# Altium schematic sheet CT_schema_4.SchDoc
size 556 x 419 mm
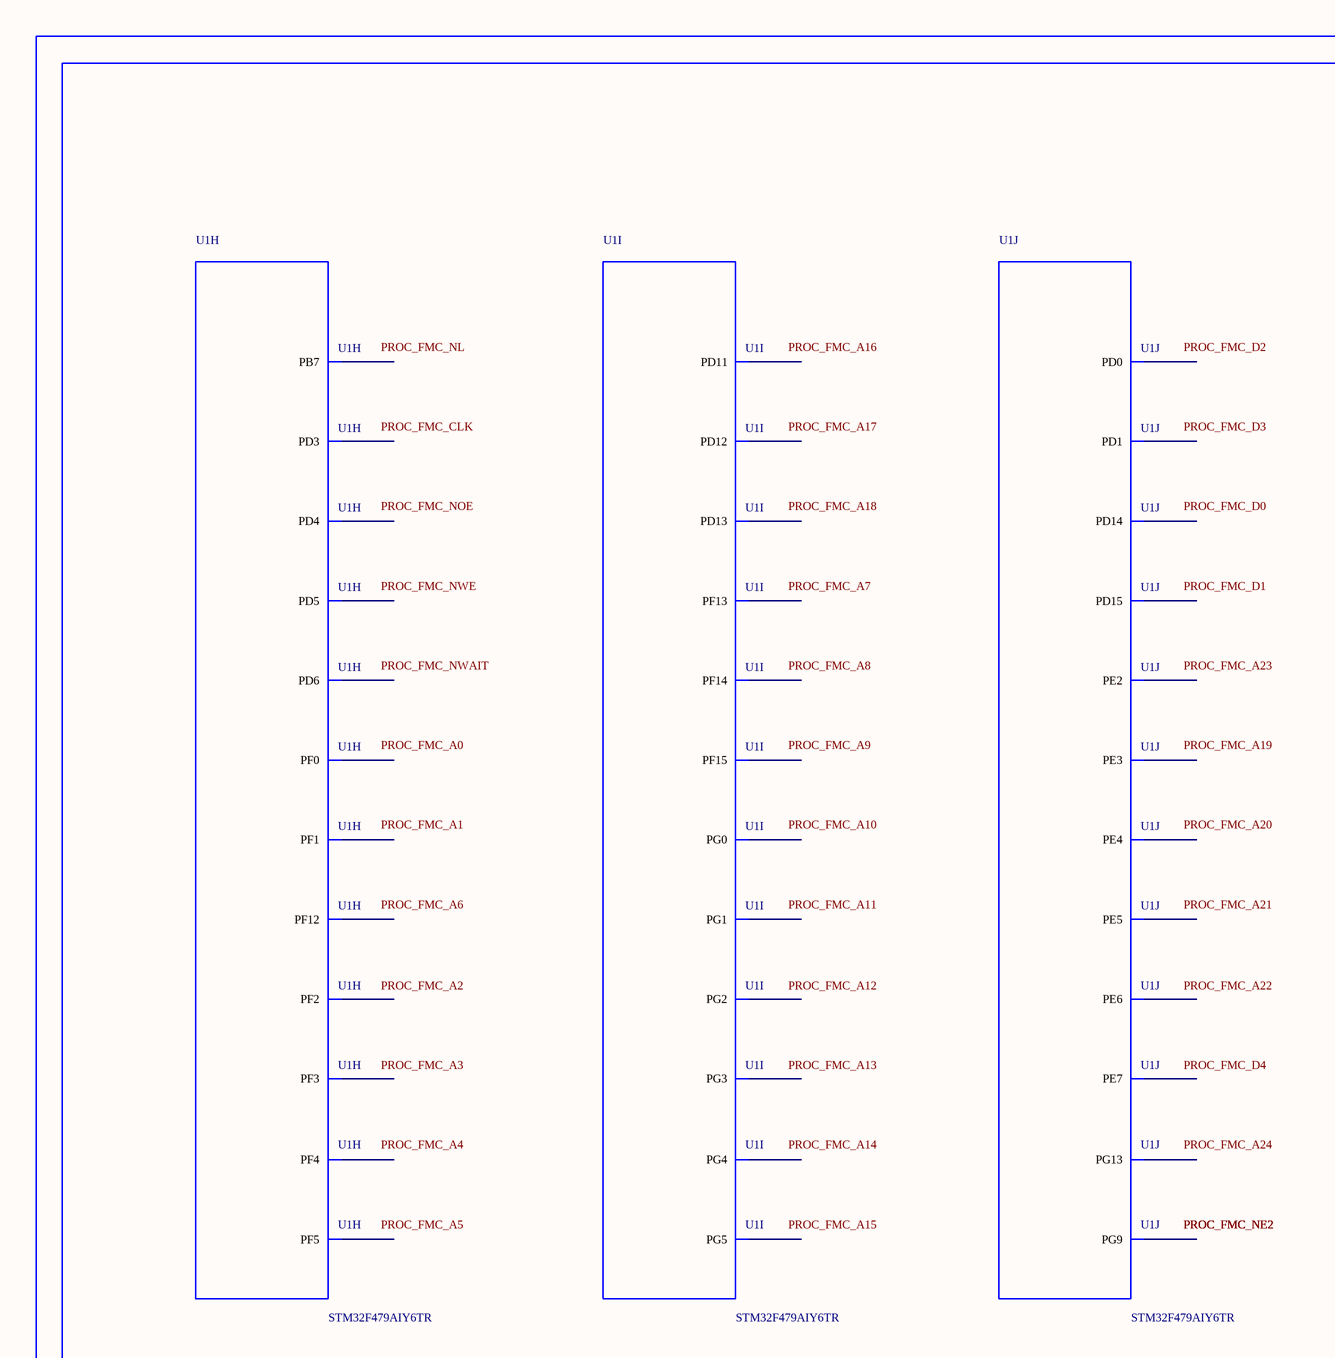
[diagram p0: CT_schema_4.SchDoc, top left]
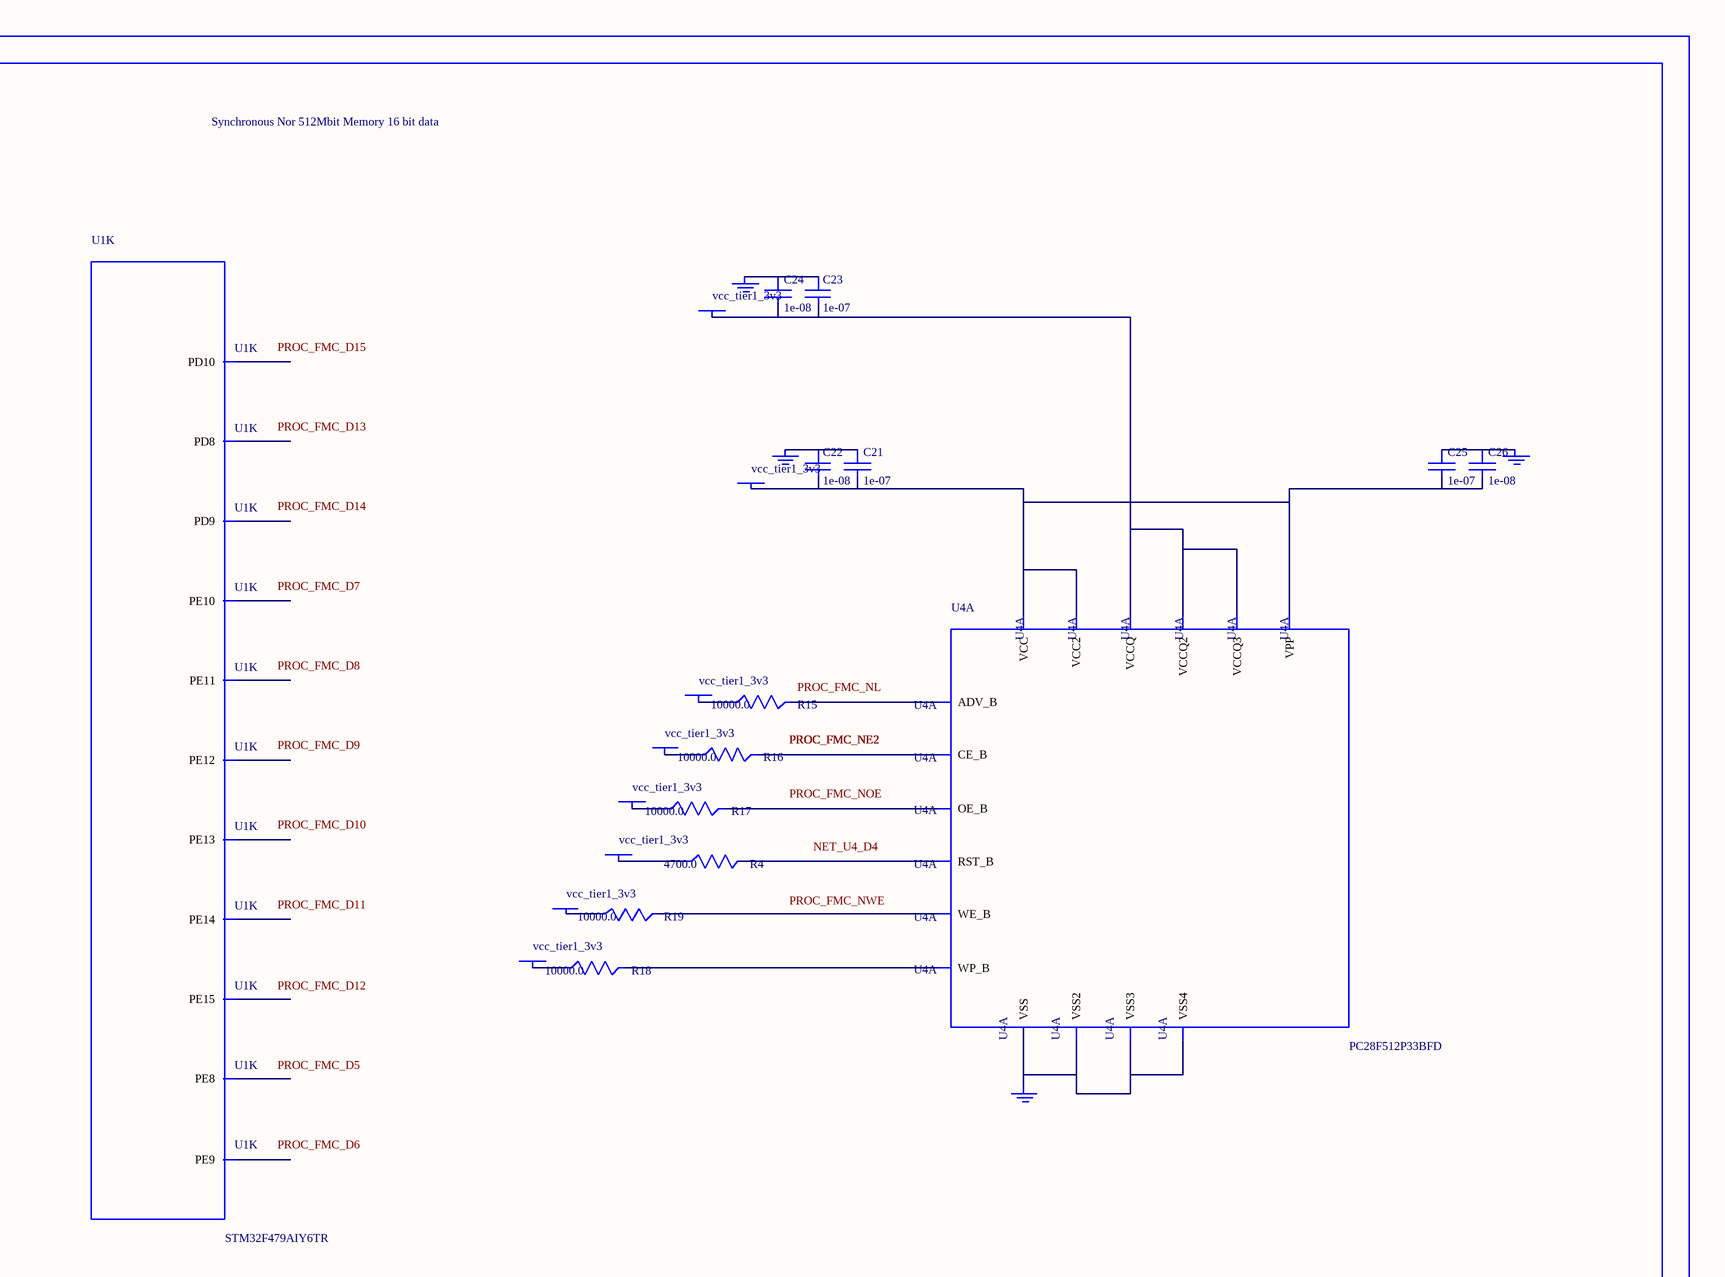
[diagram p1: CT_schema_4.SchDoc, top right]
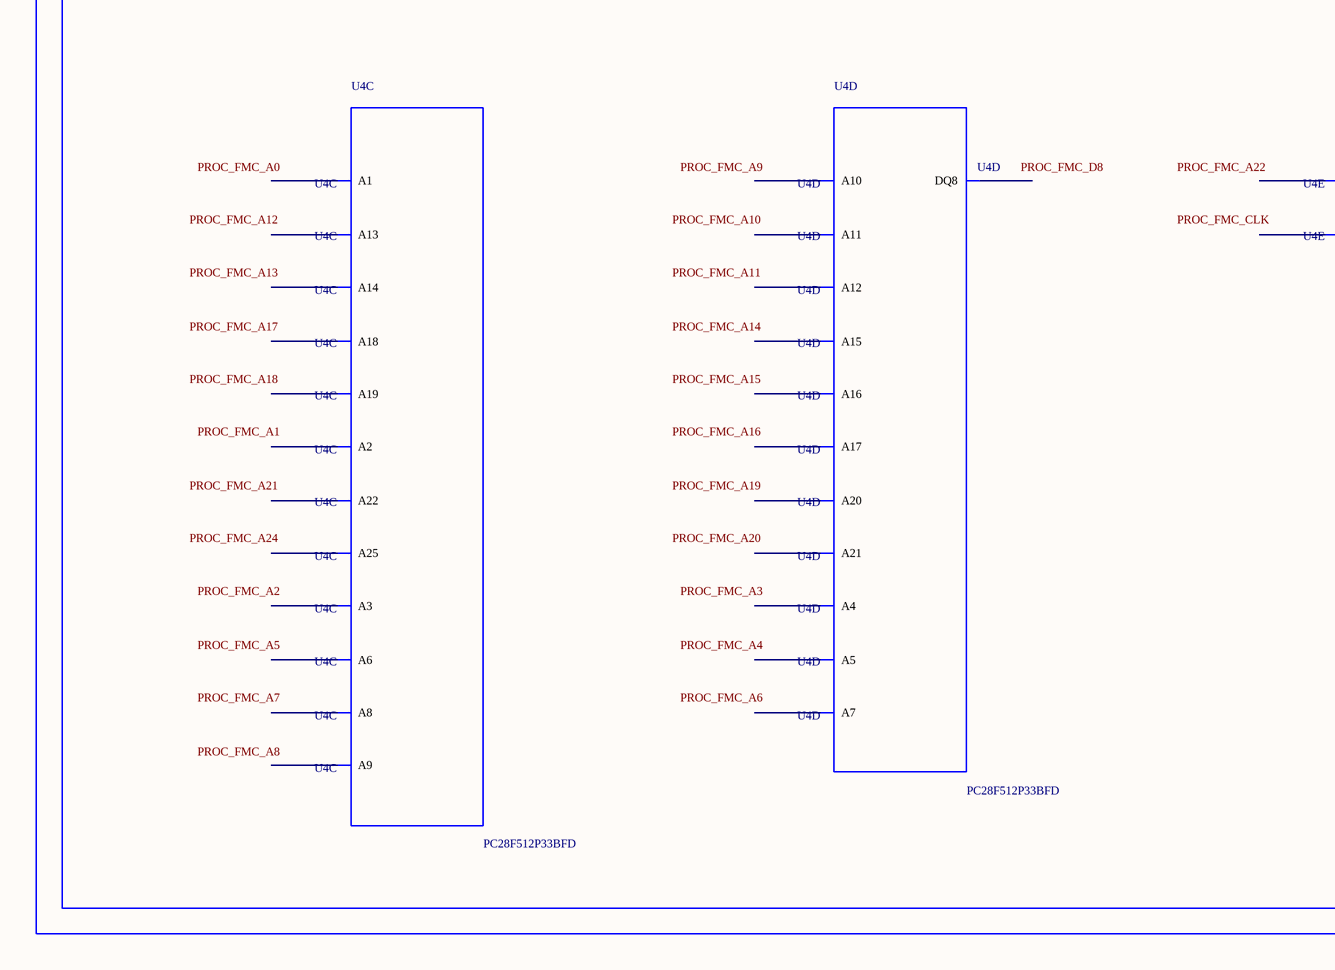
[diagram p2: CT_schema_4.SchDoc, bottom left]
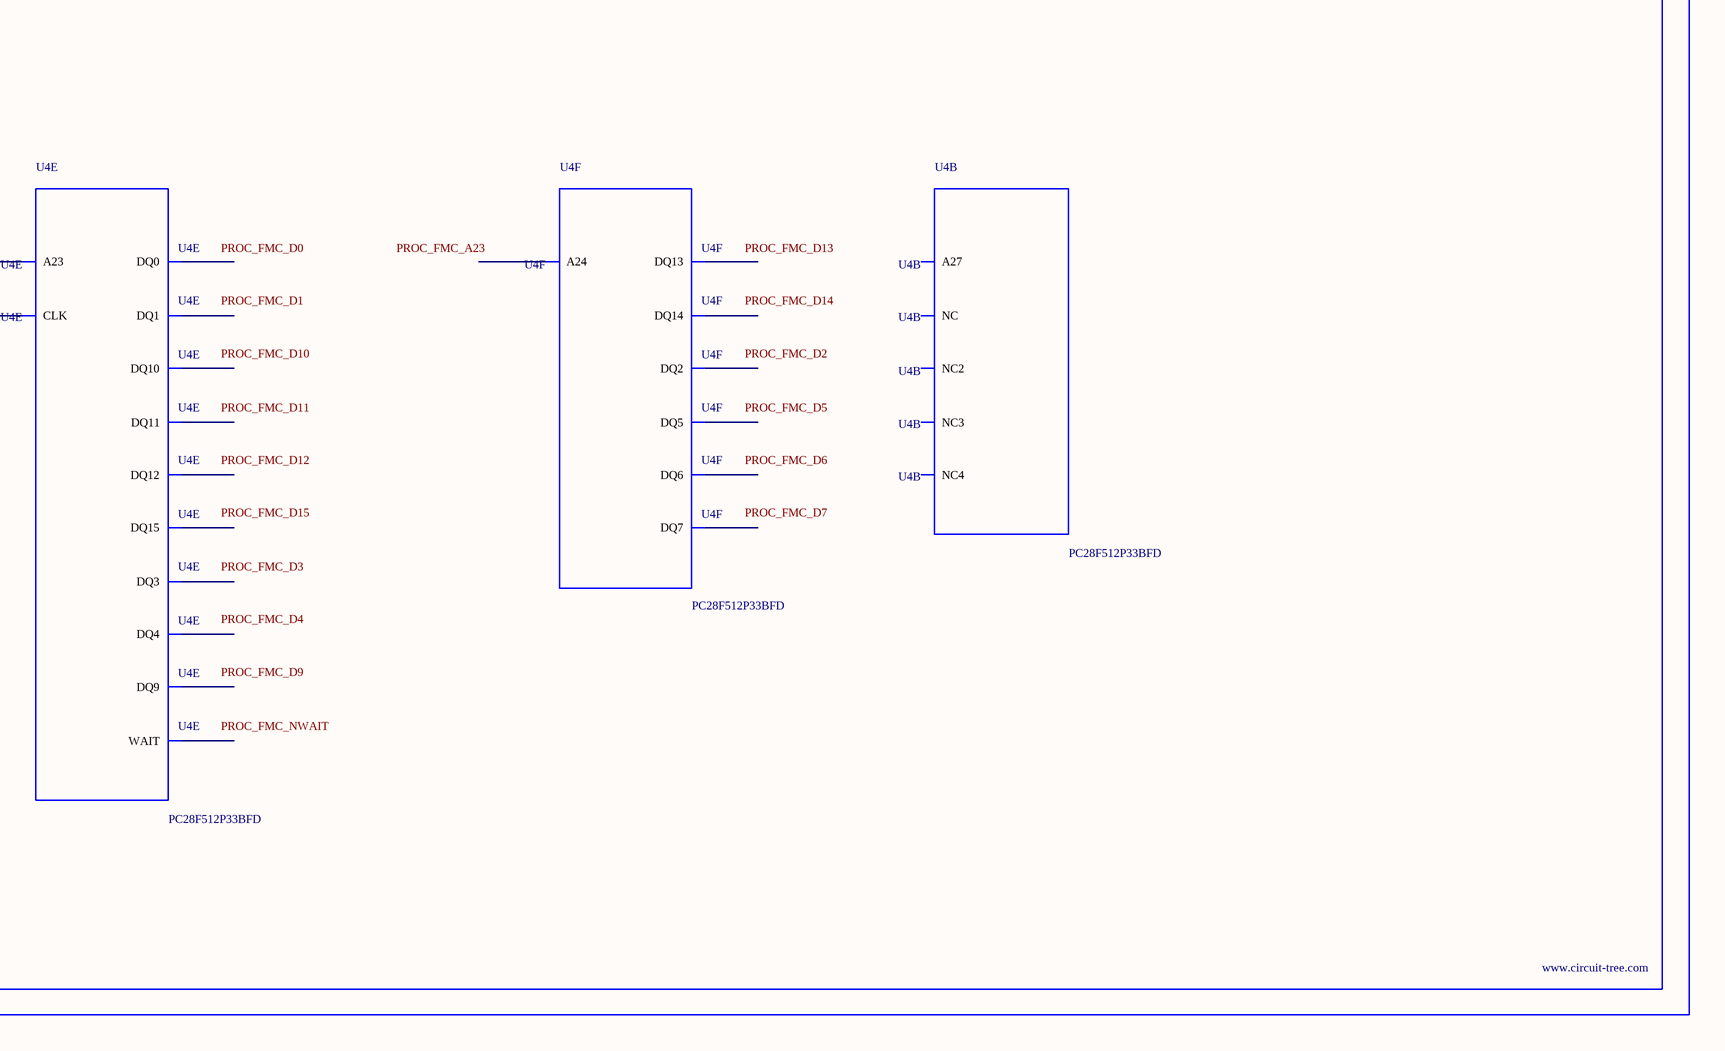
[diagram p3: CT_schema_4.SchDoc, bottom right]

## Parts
BORDER3  (no value)
C21  1e-07  [C0402]
C22  1e-08  [C0402]
C23  1e-07  [C0402]
C24  1e-08  [C0402]
C25  1e-07  [C0402]
C26  1e-08  [C0402]
GND_INSTANCE_3_0  (no value)
GND_INSTANCE_3_1  (no value)
GND_INSTANCE_3_2  (no value)
GND_INSTANCE_3_3  (no value)
POWER_INSTANCE_3_0  vcc_tier1_3v3
POWER_INSTANCE_3_1  vcc_tier1_3v3
POWER_INSTANCE_3_2  vcc_tier1_3v3
POWER_INSTANCE_3_3  vcc_tier1_3v3
POWER_INSTANCE_3_4  vcc_tier1_3v3
POWER_INSTANCE_3_5  vcc_tier1_3v3
POWER_INSTANCE_3_6  vcc_tier1_3v3
POWER_INSTANCE_3_7  vcc_tier1_3v3
R4  4700.0  [R0603]
R15  10000.0  [R0603]
R16  10000.0  [R0603]
R17  10000.0  [R0603]
R18  10000.0  [R0603]
R19  10000.0  [R0603]
U1  STM32F479AIY6TR  [WLCSP168]  (parts H,I,J,K of 13)
U4  PC28F512P33BFD  [PC28F512P33BFD]  (parts A,B,C,D,E,F of 6)

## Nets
NetC21_1: C21.1 C22.1 GND_INSTANCE_3_0.0(GND)
NetC21_2: C21.2 C22.2 C25.2 C26.2 POWER_INSTANCE_3_0.0(PWR) U4.A4(VPP) U4.A6(VCC) U4.H3(VCC2)
NetC23_1: C23.1 C24.1 GND_INSTANCE_3_1.0(GND)
NetC23_2: C23.2 C24.2 POWER_INSTANCE_3_1.0(PWR) U4.D5(VCCQ) U4.D6(VCCQ2) U4.G4(VCCQ3)
NetC25_1: C25.1 C26.1 GND_INSTANCE_3_2.0(GND)
NetGND_INSTANCE_3_3_0: GND_INSTANCE_3_3.0(GND) U4.B2(VSS) U4.H2(VSS2) U4.H4(VSS3) U4.H6(VSS4)
NetPOWER_INSTANCE_3_2_0: POWER_INSTANCE_3_2.0(PWR) R15.1
NetPOWER_INSTANCE_3_3_0: POWER_INSTANCE_3_3.0(PWR) R16.1
NetPOWER_INSTANCE_3_4_0: POWER_INSTANCE_3_4.0(PWR) R17.1
NetPOWER_INSTANCE_3_5_0: POWER_INSTANCE_3_5.0(PWR) R18.1
NetPOWER_INSTANCE_3_6_0: POWER_INSTANCE_3_6.0(PWR) R19.1
NetPOWER_INSTANCE_3_7_0: POWER_INSTANCE_3_7.0(PWR) R4.1
NetR4_2: R4.2 U4.D4(RST_B)
NetR15_2: R15.2 U4.F6(ADV_B)
NetR16_2: R16.2 U4.B4(CE_B)
NetR17_2: R17.2 U4.F8(OE_B)
NetR18_2: R18.2 U4.C6(WP_B)
NetR19_2: R19.2 U4.G8(WE_B)

Not connected (* = marked no-connect by the designer): U1 A3(PD1) A9(PB7) B4(PD4) B12(PE5) C6(PD5) C11(PE4) D6(PD3) D7(PG9) D11(PE6) E6(PD0) E7(PD6) E8(PG13) E10(PE3) F9(PE2) G1(PG5) G2(PG4) G4(PG3) G5(PG2) G10(PF0) G12(PF2) H4(PD13) H8(PF15) H10(PF1) H11(PF3) H12(PF5) J4(PD11) J5(PE14) J6(PG0) J7(PF13) J10(PF4) K6(PE9) L2(PD15) L3(PD14) L4(PD8) L6(PE13) L7(PF14) M2(PD12) M3(PD10) M6(PE12) M7(PE8) M8(PF12) N1(PD9) N6(PE11) N7(PE7) P5(PE15) P6(PE10) P7(PG1); U4 A1 A2(A6) A3(A8) A5(A13) A7(A18) A8(A22) B1(A2) B3(A9) B5(A14) B6(A25) B7(A19) B8(NC) C1(A3) C2(A7) C3(A10) C4(A12) C5(A15) C7(A20) C8(A21) D1(A4) D2(A5) D3(A11) D7(A16) D8(A17) E1(DQ8) E2(DQ1) E3(DQ9) E4(DQ3) E5(DQ4) E6(CLK) E7(DQ15) E8(NC2) F1(NC3) F2(DQ0) F3(DQ10) F4(DQ11) F5(DQ12) F7(WAIT) G1(A23) G2(NC4) G3(DQ2) G5(DQ5) G6(DQ6) G7(DQ14) H1(A27) H5(DQ13) H7(DQ7) H8(A24)

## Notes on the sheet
- Labels drawn without touching a wire or pin: NET_U4_D4, PROC_FMC_A0, PROC_FMC_A1, PROC_FMC_A2, PROC_FMC_A3, PROC_FMC_A4, PROC_FMC_A5, PROC_FMC_A6, PROC_FMC_A7, PROC_FMC_A8, PROC_FMC_A9, PROC_FMC_A10, PROC_FMC_A11, PROC_FMC_A12, PROC_FMC_A13, PROC_FMC_A14, PROC_FMC_A15, PROC_FMC_A16, PROC_FMC_A17, PROC_FMC_A18, PROC_FMC_A19, PROC_FMC_A20, PROC_FMC_A21, PROC_FMC_A22, PROC_FMC_A23, PROC_FMC_A24, PROC_FMC_CLK, PROC_FMC_D0, PROC_FMC_D1, PROC_FMC_D2, PROC_FMC_D3, PROC_FMC_D4, PROC_FMC_D5, PROC_FMC_D6, PROC_FMC_D7, PROC_FMC_D8, PROC_FMC_D9, PROC_FMC_D10, PROC_FMC_D11, PROC_FMC_D12, PROC_FMC_D13, PROC_FMC_D14, PROC_FMC_D15, PROC_FMC_NL, PROC_FMC_NOE, PROC_FMC_NWAIT, PROC_FMC_NWE

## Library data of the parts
BORDER3 = BORDER_PAGE3
C21 C23 C25 = C0402C104K3RACTU
C22 C24 C26 = C0402C103K3RAC
GND_INSTANCE_3_0-GND_INSTANCE_3_3 = GND
POWER_INSTANCE_3_0-POWER_INSTANCE_3_7 = PWR
R4 = RC0603JR-074K7L
R15-R19 = RC0603JR-0710KL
